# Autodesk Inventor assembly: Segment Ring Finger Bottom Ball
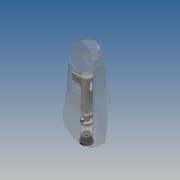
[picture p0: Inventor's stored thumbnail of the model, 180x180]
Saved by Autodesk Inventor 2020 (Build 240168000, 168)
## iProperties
Created: 2019-10
Part Number: Segment Ring Finger Bottom Ball
Document SubType Name: Assembly
Designer: yello
Author: yello
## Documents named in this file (7)
- C:\Users\yello\Documents\Mechanical Hand\Prototype 2 (Realistic Hand)\Segment Ring Finger Bottom Ball.iam
- C:\Users\yello\Documents\Mechanical Hand\Prototype 2 (Realistic Hand)\Segment Ring Finger Bottom.ipt
- C:\Users\yello\Documents\Mechanical Hand\Prototype 2 (Realistic Hand)\Lock.ipt
- C:\Users\yello\Documents\Mechanical Hand\Prototype 2 (Realistic Hand)\Push Part.ipt
- C:\Users\yello\Documents\Mechanical Hand\Prototype 2 (Realistic Hand)\Ball.ipt
- C:\Users\yello\Documents\Mechanical Hand\Prototype 2 (Realistic Hand)\Spring.ipt
- C:\Users\yello\Documents\Mechanical Hand\Prototype 2 (Realistic Hand)\Plug 2.ipt
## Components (7 placed, 6 different names)
1. Segment Ring Finger Bottom:1 — Mate:1, Mate:4, Mate:5, Mate:6, Mate:7, Mate:8, Mate:9
2. Lock:1 — Mate:2, Mate:3, Mate:4
3. Push Part:1 — Mate:1, Mate:2, Mate:3
4. Ball:1 — Mate:5
5. Ball:2 — Mate:6
6. Spring:1 — Mate:7
7. Plug 2:1 — Mate:8, Mate:9
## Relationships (9: Mate 9)
- Mate:1: Segment Ring Finger Bottom:1 ↔ Push Part:1
- Mate:2: Lock:1 ↔ Push Part:1
- Mate:3: Lock:1 ↔ Push Part:1
- Mate:4: Segment Ring Finger Bottom:1 ↔ Lock:1
- Mate:5: Segment Ring Finger Bottom:1 ↔ Ball:1
- Mate:6: Segment Ring Finger Bottom:1 ↔ Ball:2
- Mate:7: Segment Ring Finger Bottom:1 ↔ Spring:1
- Mate:8: Segment Ring Finger Bottom:1 ↔ Plug 2:1
- Mate:9: Segment Ring Finger Bottom:1 ↔ Plug 2:1
